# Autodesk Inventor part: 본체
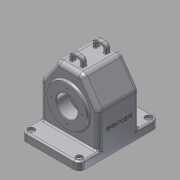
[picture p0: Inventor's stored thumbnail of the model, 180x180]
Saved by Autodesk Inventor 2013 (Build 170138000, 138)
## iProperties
Created: 2016-12
Part Number: 본체
Material: 알루미늄 6061
Document SubType Name: Modeling
Designer: Administrator
Density: 2.71 g/cm^3
Mass: 1067.05 g
Surface Area: 1138.25 cm^2
Volume: 393.747 cm^3
Author: Administrator
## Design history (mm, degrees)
sketch "스케치2"
  geometry: L1 (0, 0)-(110, 0); L2 (110, 0)-(110, 77); L3 (110, 77)-(0, 77); L4 (0, 77)-(0, 0); L5 (0, 38.5)-(110, 38.5)
  constraints: 10 end point, 2 midpoint, 2 parallel, 1 horizontal, 1 perpendicular
  dimensions: "d0" = 110 distance between parallel lines of L2 L4; "d4" = 38.5 distance between parallel lines of L1 L5
extrude "돌출1" new body sketch "스케치2" distance "d5" = 80; taper "d6" = 0 deg
sketch "스케치3"
  geometry: L1 (0, 0)-(110, 0) reference; L2 (110, 0)-(110, 80) reference; L3 (0, 80)-(110, 80) reference; L4 (0, 0)-(0, 80) reference; L5 (31.509, 125)-(78.491, 125); L6 (31.509, 125)-(0, 80); L7 (78.491, 125)-(110, 80)
  constraints: 6 end point, 1 perpendicular
  dimensions: "d7" = 125 distance between parallel lines of L1 L5; "d8" = 35 deg angle of L4 L6; "d9" = 35 deg angle of L2 L7
extrude "돌출2" join sketch "스케치3" stored distance "d10" = 80; taper "d11" = 0 deg
feature "쉘1" dims "d12" = 5
fillet "모깎기1" dims "d13" = 3
fillet "모깎기2" dims "d14" = 3
sketch "스케치4"
  geometry: L1 (-5, 69)-(-5, 8) reference; L2 (-105, 8)-(-105, 69) reference; L3 (0, 0)-(-110, 0) reference; L4 (0, 77)-(0, 0) reference; L5 (0, -36.5)-(-110, -36.5); L6 (-110, 113.5)-(0, 113.5); L7 (-5, 38.5)-(-105, 38.5); L8 (-110, 0)-(0, 0); L9 (0, 77)-(-110, 77); L10 (-110, -36.5)-(-110, 0); L11 (-110, 77)-(-110, 113.5); L12 (0, 113.5)-(0, 77); L13 (0, 0)-(0, -36.5)
  constraints: 18 end point, 6 equal length, 4 perpendicular, 2 midpoint, 1 horizontal, 1 point on line
  dimensions: "d16" = 75 distance between parallel lines of L5 L7; "d17" = 150 distance between parallel lines of L6 L5 (= 2 x d16)
extrude "돌출3" join sketch "스케치4" distance "d18" = 15; taper "d19" = 0 deg
sketch "스케치5"
  geometry: L1 (78.491, -110)-(78.491, -45) reference; L2 (46.981, 0)-(0, 0) reference; L3 (-31.509, -110)-(-31.509, -45) reference; L4 (23.491, 0)-(23.491, -125.178); L5 (-31.509, -60)-(78.491, -60); L6 (78.491, -125)-(-31.509, -125) reference; C1 r 37.5 at (23.491, -60)
  constraints: 4 end point, 2 midpoint, 2 point on line, 1 centre point, 1 parallel, 1 perpendicular
  dimensions: "d20" = 65 distance between parallel lines of L6 L5; "d21" = 75 diameter of C1
extrude "돌출4" join sketch "스케치5" distance "d22" = 5; taper "d23" = 0 deg
sketch "스케치6"
  geometry: L1 (-31.509, 110)-(-31.509, 45) reference; L2 (46.981, 0)-(0, 0) reference; L3 (78.491, 110)-(78.491, 45) reference; L4 (-31.509, 125)-(78.491, 125) reference; L5 (23.491, 125)-(23.491, 0); L6 (-31.509, 60)-(78.491, 60); C1 r 31 at (23.491, 60)
  constraints: 4 end point, 3 midpoint, 2 point on line, 1 centre point, 1 perpendicular
  dimensions: "d24" = 65 distance between parallel lines of L6 L4; "d25" = 62 diameter of C1
extrude "돌출5" join sketch "스케치6" distance "d26" = 10; taper "d27" = 0 deg
fillet "모깎기3" dims "d28" = 10
node "작업 평면1"
sketch "스케치7"
  geometry: L1 (-117, 41.5)-(-77.478, 41.5) reference; L2 (-77.478, 41.5)-(0, 41.5) reference; L3 (-102.5, 31.5)-(-27.5, 31.5) reference; L4 (-65, 31.5)-(-65, 55.5); L5 (-65, 55.5)-(-92, 55.5); L6 (-92, 55.5)-(-106, 41.5); L7 (-106, 41.5)-(-65, 41.5); 1 further point
  constraints: 8 end point, 3 point on line, 2 perpendicular, 1 midpoint
  dimensions: "d29" = 24 distance of L4.start L4.end; "d32" = 54 diameter of L5.end L4; "d34" = 45 deg angle of L6 L5
revolve "회전1" sketch "스케치7" stored, may be unused: angle "d35" = 90 deg
sketch "스케치8"
  geometry: C1 r 37.5 at (0, 0) reference; C2 r 20 at (0, 0); 1 further point
  constraints: 1 centre point, 1 coincident
  dimensions: "d36" = 40 diameter of C2
extrude "돌출6" cut sketch "스케치8" stored distance "d38" = 10; taper "d39" = 0 deg
fillet "모깎기4" dims "d40" = 10
fillet "모깎기5" dims "d41" = 8
fillet "모깎기6" dims "d42" = 3
sketch "스케치9"
  geometry: L1 (107, 103.5)-(107, 78.798) reference; L2 (10, 110.5)-(100, 110.5) reference; L3 (3, 78.798)-(3, 103.5) reference; L4 (102, 80)-(8, 80) reference; C1 r 6 at (10, -26.5); C2 r 6 at (100, -26.5); C3 r 6 at (100, 103.5); C4 r 6 at (10, 103.5); A1 r 7 centre (10, -26.5) between (3, -26.5) and (10, -33.5) reference; A2 r 7 centre (100, -26.5) between (100, -33.5) and (107, -26.5) reference; A3 r 11 centre (102, 69) between (107, 78.798) and (102, 80) reference; A4 r 7 centre (100, 103.5) between (107, 103.5) and (100, 110.5) reference; A5 r 7 centre (10, 103.5) between (10, 110.5) and (3, 103.5) reference; A6 r 11 centre (8, 69) between (8, 80) and (3, 78.798) reference; 1 further point
  constraints: 4 centre point, 4 coincident, 3 equal radius
  dimensions: "d43" = 12 diameter of C1
extrude "돌출7" cut sketch "스케치9" distance "d45" = 5; taper "d46" = 0 deg
sketch "스케치10"
  geometry: C1 r 6 at (0, 0) reference; C2 r 2.5 at (0, 0); C3 r 6 at (-90, 130) reference; C4 r 6 at (0, 130) reference; C5 r 6 at (-90, 0) reference; C6 r 2.5 at (-90, 0); C7 r 2.5 at (-90, 130); C8 r 2.5 at (0, 130); 1 further point
  constraints: 4 centre point, 4 coincident, 3 equal radius
  dimensions: "d47" = 5 diameter of C2
extrude "돌출8" cut sketch "스케치10" stored distance "d49" = 5; taper "d50" = 0 deg
fillet "모깎기7" dims "d51" = 3
chamfer "모따기1" distance "d52" = 1; stored, may be unused: second distance "d53" = 2, angle "d54" = 45 deg
fillet "모깎기8" dims "d55" = 3
sketch "스케치11" dims "d56" = 58
  geometry: C1 r 37.5 at (0, 0) reference; C2 r 21 at (0, 0) reference; C3 r 1.5 at (0, 29); 2 further points
  constraints: 2 vertical alignment, 1 centre point, 1 coincident, 2 other
  dimensions: "d58" = 3 diameter of C3
hole "구멍1" sketch "스케치11" at (0, 29) diameter "d59" = 2.459; stored, may be unused: countersink angle "d63" = 90 deg, drill point angle "d65" = 118 deg; dims "d60" = 6, "d61" = 4, "d62" = 2, "d64" = 8
sketch "스케치12" dims "d69" = 52
  geometry: C1 r 31 at (0, 0) reference; C2 r 21 at (0, 0) reference; C3 r 1.5 at (0, 26); 2 further points
  constraints: 2 vertical alignment, 1 centre point, 1 coincident, 2 other
  dimensions: "d71" = 3 diameter of C3
hole "구멍2" sketch "스케치12" at (0, 26) diameter "d72" = 2.459; stored, may be unused: countersink angle "d76" = 90 deg, drill point angle "d78" = 118 deg; dims "d73" = 6, "d74" = 4, "d75" = 2, "d77" = 8
sketch "스케치14"
  geometry: L1 (63.285, 44.5)-(-26.715, 44.5) reference; L2 (-26.715, -105.5)-(63.285, -105.5) reference; L3 (18.285, 44.5)-(18.285, -105.5); L4 (5.785, -4.5)-(30.785, -4.5); L5 (30.785, -4.5)-(30.785, -56.5); L6 (30.785, -56.5)-(5.785, -56.5); L7 (5.785, -56.5)-(5.785, -4.5); L8 (-36.715, 0)-(-36.715, -61) reference; L9 (73.285, -61)-(73.285, 0) reference; L10 (-36.715, -30.5)-(73.285, -30.5); 1 further point
  constraints: 12 end point, 4 midpoint, 2 parallel, 1 horizontal, 1 perpendicular
  dimensions: "d84" = 52 distance between parallel lines of L6 L4; "d86" = 26 distance between parallel lines of L10 L4 (= 0.5 x d84); "d87" = 25 distance between parallel lines of L5 L7; "d88" = 12.5 distance between parallel lines of L7 L3 (= 0.5 x d87)
extrude "돌출9" join sketch "스케치14" distance "d89" = 15; taper "d90" = 0 deg
sketch "스케치15"
  geometry: L1 (5.785, -4.5)-(5.785, -56.5) reference; L2 (30.785, -56.5)-(30.785, -4.5) reference; L3 (-36.715, 0)-(-36.715, -61) reference; L4 (73.285, -61)-(73.285, 0) reference; L5 (-36.715, -30.5)-(73.285, -30.5); L6 (5.785, -12.5)-(30.785, -12.5); L7 (30.785, -12.5)-(30.785, -48.5); L8 (30.785, -48.5)-(5.785, -48.5); L9 (5.785, -48.5)-(5.785, -12.5); 1 further point
  constraints: 10 end point, 2 midpoint, 2 parallel, 2 point on line, 1 horizontal, 1 perpendicular
  dimensions: "d91" = 36 distance between parallel lines of L8 L6; "d93" = 18 distance between parallel lines of L8 L5 (= 0.5 x d91)
extrude "돌출10" cut sketch "스케치15" stored distance "d94" = 15; taper "d95" = 0 deg
fillet "모깎기9" dims "d98" = 8
sketch "스케치17"
  geometry: L1 (0, 0)-(0, 7) reference; L2 (25, 0)-(0, 0) reference; L3 (25, 0)-(25, 7) reference; L4 (8, 15)-(17, 15) reference; L5 (20, 7)-(20, 0); L6 (5, 0)-(5, 7); L7 (8, 10)-(17, 10); L8 (30.785, 0)-(-5.785, 0) reference; A1 r 8 centre (8, 7) between (8, 15) and (0, 7) reference; A2 r 8 centre (17, 7) between (25, 7) and (17, 15) reference; A3 r 3 centre (17, 7) between (20, 7) and (17, 10); A4 r 3 centre (8, 7) between (8, 10) and (5, 7); 1 further point
  constraints: 6 end point, 4 point on circle, 2 centre point, 2 point on line, 1 perpendicular, 3 other
  dimensions: "d99" = 5 radial gap between concentric circles of A2 A3; "d100" = 5 radial gap between concentric circles of A1 A4
extrude "돌출11" cut sketch "스케치17" stored distance "d101" = 15; taper "d102" = 0 deg
fillet "모깎기10" dims "d103" = 1
fillet "모깎기11" dims "d104" = 1
sketch "스케치18"
  geometry: L1 (0, 130)-(0, 0) reference; L2 (-28.775, 40.113)-(-28.775, 89.887); L3 (-28.775, 89.887)-(-61.225, 89.887); L4 (-61.225, 89.887)-(-61.225, 40.113); L5 (-61.225, 40.113)-(-28.775, 40.113); L6 (-45, 40.113)-(-45, 89.887); L7 (-28.775, 65)-(-61.225, 65); L8 (-125, 95.5)-(-125, 34.5) reference; L9 (-125, 65)-(0, 65); 1 further point
  constraints: 6 end point, 6 midpoint, 2 other
  dimensions: "d105" = 0 distance between parallel lines of L7 L9; "d107" = 45 distance between parallel lines of L1 L6
feature "엠보싱1" sketch "스케치18" dims "d108" = 0.5, "d109" = 0
node "솔리드1"
pattern_circular "원형 패턴1" dims angle "d67" = 360 deg
pattern_circular "원형 패턴2" dims angle "d80" = 360 deg
node "투영된 루프1"
node "투영된 루프2"
node "투영된 루프3"
node "투영된 루프4"
other parameters: "d15" = 0
